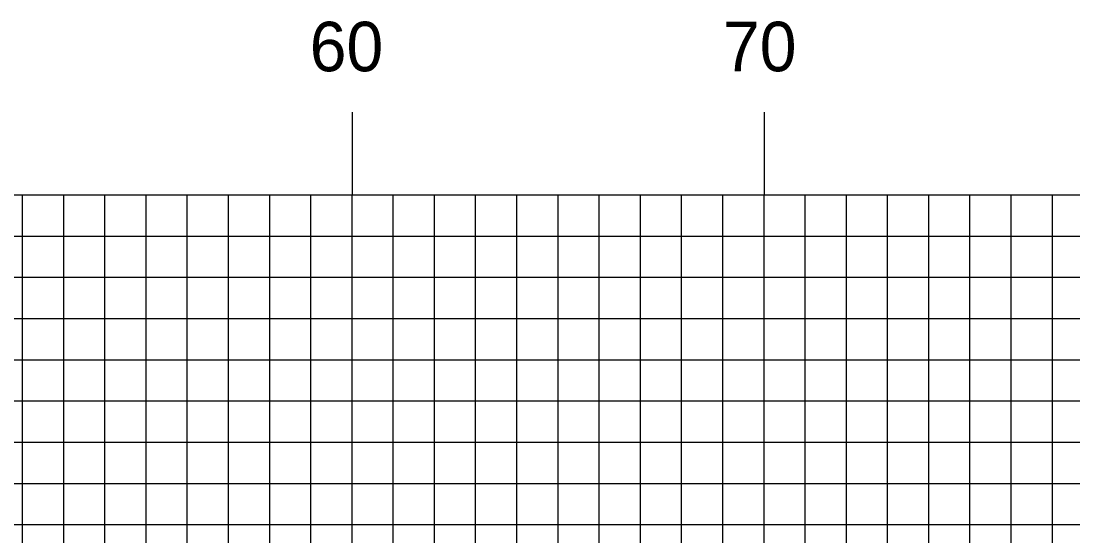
# Model space of a CAD drawing. Extents: x 1782254 to 1782597, y 442591 to 442811.
# Drawn here: x 1782471.4 to 1782496.93, y 442635.39 to 442647.88 of the extents above; entities that cross this region are included whole.
import ezdxf

# ---------------------------------------------------------------- set-up
doc = ezdxf.new("R2010")
doc.units = 0
for name, color, linetype in [('H_V ANNOTATION', 7, 'Continuous'), ('MAJOR', 7, 'Continuous'), ('MINOR', 7, 'Continuous')]:
    doc.layers.add(name, color=color, linetype=linetype)

msp = doc.modelspace()

# ---------------------------------------------------------------- linework, layer by layer
at = {"layer": 'MAJOR'}
for p, q in [((1782479.434, 442645.669), (1782479.434, 442643.665)), ((1782489.434, 442645.669), (1782489.434, 442643.665)), ((1782279.434, 442643.665), (1782559.434, 442643.665)), ((1782279.434, 442643.665), (1782559.434, 442643.665)), ((1782479.434, 442608.665), (1782479.434, 442643.665)), ((1782489.434, 442608.665), (1782489.434, 442643.665)), ((1782279.434, 442638.665), (1782559.434, 442638.665))]:
    msp.add_line(p, q, dxfattribs=at)
at = {"layer": 'MINOR'}
for p, q in [((1782471.434, 442608.665), (1782471.434, 442643.665)), ((1782472.434, 442608.665), (1782472.434, 442643.665)), ((1782473.434, 442608.665), (1782473.434, 442643.665)), ((1782474.434, 442608.665), (1782474.434, 442643.665)), ((1782475.434, 442608.665), (1782475.434, 442643.665)), ((1782476.434, 442608.665), (1782476.434, 442643.665)), ((1782477.434, 442608.665), (1782477.434, 442643.665)), ((1782478.434, 442608.665), (1782478.434, 442643.665)), ((1782480.434, 442608.665), (1782480.434, 442643.665)), ((1782481.434, 442608.665), (1782481.434, 442643.665)), ((1782482.434, 442608.665), (1782482.434, 442643.665)), ((1782483.434, 442608.665), (1782483.434, 442643.665)), ((1782484.434, 442608.665), (1782484.434, 442643.665)), ((1782485.434, 442608.665), (1782485.434, 442643.665)), ((1782486.434, 442608.665), (1782486.434, 442643.665)), ((1782487.434, 442608.665), (1782487.434, 442643.665)), ((1782488.434, 442608.665), (1782488.434, 442643.665)), ((1782490.434, 442608.665), (1782490.434, 442643.665)), ((1782491.434, 442608.665), (1782491.434, 442643.665)), ((1782492.434, 442608.665), (1782492.434, 442643.665)), ((1782493.434, 442608.665), (1782493.434, 442643.665)), ((1782494.434, 442608.665), (1782494.434, 442643.665)), ((1782495.434, 442608.665), (1782495.434, 442643.665)), ((1782496.434, 442608.665), (1782496.434, 442643.665)), ((1782279.434, 442642.665), (1782559.434, 442642.665)), ((1782279.434, 442641.665), (1782559.434, 442641.665)), ((1782279.434, 442640.665), (1782559.434, 442640.665)), ((1782279.434, 442639.665), (1782559.434, 442639.665)), ((1782279.434, 442637.665), (1782559.434, 442637.665)), ((1782279.434, 442636.665), (1782559.434, 442636.665)), ((1782279.434, 442635.665), (1782559.434, 442635.665))]:
    msp.add_line(p, q, dxfattribs=at)

# ---------------------------------------------------------------- texts
at = {"layer": 'H_V ANNOTATION'}
for s, p in [('60', (1782478.406, 442646.665)), ('70', (1782488.438, 442646.665))]:
    msp.add_text(s, height=1.2, dxfattribs=at).set_placement(p)

doc.saveas('drawing.dxf')
